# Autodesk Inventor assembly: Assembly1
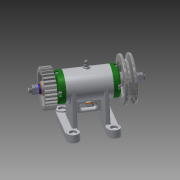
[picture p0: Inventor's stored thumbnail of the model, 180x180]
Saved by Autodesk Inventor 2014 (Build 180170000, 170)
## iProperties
Created: 2015-11
Part Number: Assembly1
Document SubType Name: Assembly
Designer: user
Author: user
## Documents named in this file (16)
- C:\Users\user\Desktop\451110V1011\Assembly1.iam
- C:\Users\user\Desktop\451110V1011\451110V1011본체.ipt
- C:\Users\user\Desktop\451110V1011\커버.ipt
- C:\Users\user\Desktop\451110V1011\베어링 15 x 32 x 9.ipt
- C:\Users\user\Desktop\451110V1011\축.ipt
- C:\Users\user\Desktop\451110V1011\오일 실 15 25 7.ipt
- C:\Users\user\Desktop\451110V1011\볼트 M4 x 12.ipt
- C:\Users\user\Desktop\451110V1011\키 3 x 3 x 12.ipt
- C:\Users\user\Desktop\451110V1011\V벨트풀리.ipt
- C:\Users\user\Desktop\451110V1011\스퍼기어.ipt
- C:\Users\user\Desktop\451110V1011\와셔 8x17.ipt
- C:\Users\user\Desktop\451110V1011\스프링와셔 8.ipt
- C:\Users\user\Desktop\451110V1011\너트 M 8.ipt
- C:\Users\user\Desktop\451110V1011\와셔 6x11.5.ipt
- C:\Users\user\Desktop\451110V1011\볼트 M 6 x 8.ipt
- C:\Users\user\Desktop\451110V1011\니플 M 6 x 0.75.ipt
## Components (12 placed, 4 different names)
1. 451110V1011본체:1 — Insert:1, Mate:1, Mate:2, Mate:3, Insert:2, Insert:3, Insert:6, Insert:19
2. KS B 2023 6002 - 15 x 32 x 9:1 — Insert:2
3. KS B 2023 6002 - 15 x 32 x 9:2 — Insert:3, Insert:23
4. V벨트풀리:1 — Insert:14, Mate:7, Insert:15
5. ISO 4762 M4 x 12:4 — Insert:22
6. ISO 4762 M4 x 12:5
7. ISO 4762 M4 x 12:6
8. ISO 4762 M4 x 12:7
9. ISO 4762 M4 x 12:3 — Insert:21
10. ISO 4762 M4 x 12:8
11. ISO 4762 M4 x 12:9
12. ISO 4762 M4 x 12:10
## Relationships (14: Insert 10, Mate 4)
- Insert:1: 451110V1011본체:1
- Mate:1: 451110V1011본체:1
- Mate:2: 451110V1011본체:1
- Mate:3: 451110V1011본체:1
- Insert:2: 451110V1011본체:1 ↔ KS B 2023 6002 - 15 x 32 x 9:1
- Insert:3: 451110V1011본체:1 ↔ KS B 2023 6002 - 15 x 32 x 9:2
- Insert:6: 451110V1011본체:1
- Insert:14: V벨트풀리:1
- Mate:7: V벨트풀리:1
- Insert:15: V벨트풀리:1
- Insert:19: 451110V1011본체:1
- Insert:21: ISO 4762 M4 x 12:3
- Insert:22: ISO 4762 M4 x 12:4
- Insert:23: KS B 2023 6002 - 15 x 32 x 9:2
